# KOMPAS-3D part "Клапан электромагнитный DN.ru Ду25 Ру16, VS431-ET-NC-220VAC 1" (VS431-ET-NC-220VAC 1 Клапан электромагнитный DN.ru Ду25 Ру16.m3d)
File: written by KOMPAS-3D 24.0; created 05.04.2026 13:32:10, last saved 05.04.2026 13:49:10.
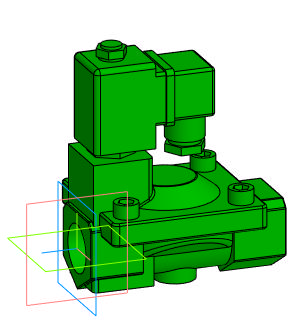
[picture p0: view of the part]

Document properties: Автор: artio; Полное имя файла: C:\Users\artio\OneDrive\Рабочий стол\Клапан электромагнитный DN.ru\VS431\VS431-ET-NC\VS431-ET-NC-220VAC\Ду25\VS431-ET-NC-220VAC 1 Клапан электромагнитный DN.ru Ду25 Ру16.m3d

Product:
- Body: Тело 1  | qty 1
    Масса: 1.729172
- Part/product: Клапан электромагнитный DN.ru Ду25 Ру16  | designation VS431-ET-NC-220VAC 1
    Масса: 1.267
    Раздел спецификации: Прочие изделия
    Примечание: D130-04707
    additional columns: ef56311e-7521-43dc-8291-0e6108b3d81d; artio; c; Шероховатость не задана; Да

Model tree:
1. Операция без истории:1

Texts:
  VS431-ET-NC-220VAC 1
